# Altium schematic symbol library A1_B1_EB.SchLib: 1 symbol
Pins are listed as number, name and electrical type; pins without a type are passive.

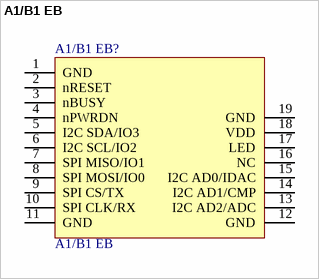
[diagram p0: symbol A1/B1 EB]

## A1/B1 EB
designator A1/B1 EB?  (no BOM)
A1/B1 Expansion Board; Manufacturer: Eccel Technology Ltd; Manufacturer P/N: A1/B1 EB v2.1
footprint A1_B1_EB
pins: 1 GND, 2 nRESET, 3 nBUSY, 4 nPWRDN, 5 I2C SDA/IO3, 6 I2C SCL/IO2, 7 SPI MISO/IO1, 8 SPI MOSI/IO0, 9 SPI CS/TX, 10 SPI CLK/RX, 11 GND, 12 GND, 13 I2C AD2/ADC, 14 I2C AD1/CMP, 15 I2C AD0/IDAC, 16 NC, 17 LED, 18 VDD, 19 GND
